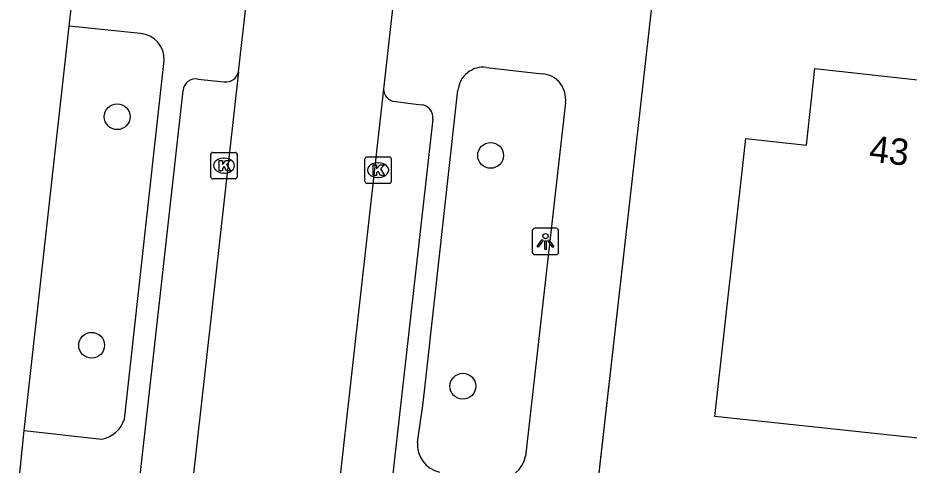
# Model space of a CAD drawing. Extents: x 162026 to 163499, y 387297 to 388169.
# Drawn here: x 162278.65 to 162312.4, y 387793.2 to 387810.16 of the extents above; entities that cross this region are included whole.
import ezdxf

# ---------------------------------------------------------------- set-up
doc = ezdxf.new("R2010")
doc.units = 0
for name, color, linetype in [('IMGEO_Boom', 7, 'Continuous'), ('IMGEO_Fietspad_gesloten', 7, 'Continuous'), ('IMGEO_Kolk', 7, 'Continuous'), ('IMGEO_Lichtpunt', 7, 'Continuous'), ('IMGEO_Muur', 7, 'Continuous'), ('IMGEO_Pand', 7, 'Continuous'), ('IMGEO_Pand_nummerreeks', 7, 'Continuous'), ('IMGEO_Rijbaan_lokaal_gesloten', 7, 'Continuous'), ('IMGEO_Voetpad_open', 7, 'Continuous')]:
    doc.layers.add(name, color=color, linetype=linetype)

msp = doc.modelspace()

# ---------------------------------------------------------------- linework, layer by layer
at = {"layer": 'IMGEO_Boom'}
for centre in [(162282.408, 387806.409), (162296.549, 387804.942), (162281.44, 387797.746), (162295.498, 387796.193)]:
    msp.add_circle(centre, 0.489, dxfattribs=at)
at = {"layer": 'IMGEO_Fietspad_gesloten'}
for points in [[(162280.59, 387809.842), (162281.546, 387818.246), (162282.058, 387818.211)], [(162278.879, 387794.52), (162280.59, 387809.842)], [(162278.652, 387792.276), (162278.879, 387794.52)]]:
    msp.add_lwpolyline(points, dxfattribs=at)
at = {"layer": 'IMGEO_Kolk'}
for p, q in [((162285.95, 387804.129), (162285.95, 387804.981)), ((162286.025, 387805.055), (162286.877, 387805.055)), ((162286.438, 387804.835), (162286.463, 387804.835)), ((162286.951, 387804.981), (162286.951, 387804.129)), ((162291.786, 387803.957), (162291.786, 387804.809)), ((162291.861, 387804.883), (162292.713, 387804.883)), ((162292.787, 387804.809), (162292.787, 387803.957)), ((162292.274, 387804.663), (162292.299, 387804.663)), ((162286.461, 387804.275), (162286.436, 387804.275)), ((162292.297, 387804.103), (162292.272, 387804.103)), ((162286.877, 387804.055), (162286.025, 387804.055)), ((162292.713, 387803.883), (162291.861, 387803.883))]:
    msp.add_line(p, q, dxfattribs=at)
for points in [[(162285.95, 387804.129), (162285.95, 387804.981)], [(162286.025, 387805.055), (162286.877, 387805.055)], [(162286.951, 387804.981), (162286.951, 387804.129)], [(162291.786, 387803.957), (162291.786, 387804.809)], [(162291.861, 387804.883), (162292.713, 387804.883)], [(162292.787, 387804.809), (162292.787, 387803.957)], [(162286.271, 387804.755), (162286.394, 387804.755), (162286.394, 387804.604), (162286.524, 387804.755), (162286.688, 387804.755), (162286.542, 387804.604), (162286.695, 387804.355), (162286.543, 387804.355), (162286.458, 387804.519), (162286.394, 387804.452), (162286.394, 387804.355), (162286.271, 387804.355), (162286.271, 387804.755)], [(162292.107, 387804.583), (162292.23, 387804.583), (162292.23, 387804.432), (162292.36, 387804.583), (162292.524, 387804.583), (162292.378, 387804.432), (162292.531, 387804.183), (162292.379, 387804.183), (162292.294, 387804.347), (162292.23, 387804.28), (162292.23, 387804.183), (162292.107, 387804.183), (162292.107, 387804.583)], [(162286.877, 387804.055), (162286.025, 387804.055)], [(162292.713, 387803.883), (162291.861, 387803.883)]]:
    msp.add_lwpolyline(points, dxfattribs=at)
for centre, start, end in [((162286.027, 387804.979), 91.552, 178.448), ((162286.027, 387804.979), 91.552, 178.448), ((162286.875, 387804.979), 1.552, 88.448), ((162286.875, 387804.979), 1.552, 88.448), ((162291.863, 387804.807), 91.552, 178.448), ((162291.863, 387804.807), 91.552, 178.448), ((162292.711, 387804.807), 1.552, 88.448), ((162292.711, 387804.807), 1.552, 88.448), ((162286.027, 387804.131), 181.552, 268.448), ((162286.027, 387804.131), 181.552, 268.448), ((162286.875, 387804.131), 271.552, 358.448), ((162286.875, 387804.131), 271.552, 358.448), ((162291.863, 387803.959), 181.552, 268.448), ((162291.863, 387803.959), 181.552, 268.448), ((162292.711, 387803.959), 271.552, 358.448), ((162292.711, 387803.959), 271.552, 358.448)]:
    msp.add_arc(centre, 0.0765, start, end, dxfattribs=at)
for centre, major_axis, ratio, start_param, end_param in [((162286.437, 387804.555), (-0.387, 0.002), 0.722429, 4.712389, 7.853982), ((162286.462, 387804.555), (-0.39, 0.002), 0.717154, 1.570796, 4.712389), ((162292.273, 387804.383), (-0.387, 0.002), 0.722429, 4.712389, 7.853982), ((162292.298, 387804.383), (-0.39, 0.002), 0.717154, 1.570796, 4.712389)]:
    msp.add_ellipse(centre, major_axis=major_axis, ratio=ratio, start_param=start_param, end_param=end_param, dxfattribs=at)
at = {"layer": 'IMGEO_Lichtpunt'}
for p, q in [((162298.128, 387802.085), (162298.128, 387801.278)), ((162298.128, 387802.085), (162298.128, 387801.278)), ((162299.03, 387802.18), (162298.222, 387802.18)), ((162299.03, 387802.18), (162298.222, 387802.18)), ((162299.124, 387801.278), (162299.124, 387802.085)), ((162299.124, 387801.278), (162299.124, 387802.085)), ((162298.222, 387801.184), (162299.03, 387801.184)), ((162298.222, 387801.184), (162299.03, 387801.184))]:
    msp.add_line(p, q, dxfattribs=at)
for points in [[(162298.502, 387801.749), (162298.541, 387801.721), (162298.353, 387801.459), (162298.315, 387801.486), (162298.502, 387801.749)], [(162298.714, 387801.721), (162298.752, 387801.748), (162298.939, 387801.486), (162298.9, 387801.458), (162298.714, 387801.721)], [(162298.604, 387801.701), (162298.651, 387801.701), (162298.651, 387801.379), (162298.604, 387801.379), (162298.604, 387801.701)]]:
    msp.add_lwpolyline(points, dxfattribs=at)
msp.add_circle((162298.627, 387801.883), 0.0994, dxfattribs=at)
for centre, start, end in [((162298.222, 387802.085), 90, 180), ((162298.222, 387802.085), 90, 180), ((162299.03, 387802.085), 0, 90), ((162299.03, 387802.085), 0, 90), ((162298.222, 387801.278), 180, 270), ((162298.222, 387801.278), 180, 270), ((162299.03, 387801.278), 270, 0), ((162299.03, 387801.278), 270, 360)]:
    msp.add_arc(centre, 0.0946, start, end, dxfattribs=at)
at = {"layer": 'IMGEO_Muur'}
msp.add_lwpolyline([(162300.27, 387789.459), (162302.135, 387805.96)], dxfattribs=at)
at = {"layer": 'IMGEO_Pand'}
msp.add_lwpolyline([(162314.61, 387799.534), (162314.475, 387798.313), (162314.036, 387794.079), (162305.036, 387795.05), (162306.214, 387805.585), (162308.506, 387805.337), (162308.825, 387808.234), (162315.35, 387807.516)], dxfattribs=at)
at = {"layer": 'IMGEO_Rijbaan_lokaal_gesloten'}
for points in [[(162287.006, 387808.114), (162287.762, 387814.78)], [(162292.904, 387811.196), (162292.493, 387807.458)], [(162287.006, 387808.114), (162280.695, 387751.699), (162277.051, 387719.431), (162275.389, 387704.712)], [(162292.493, 387807.458), (162285.406, 387744.3), (162281.03, 387705.382)]]:
    msp.add_lwpolyline(points, dxfattribs=at)
at = {"layer": 'IMGEO_Voetpad_open'}
for points in [[(162300.281, 387789.552), (162302.135, 387805.96), (162302.745, 387811.357)], [(162283.29, 387809.569), (162280.59, 387809.842)], [(162282.682, 387794.949), (162284.192, 387808.546)], [(162296.389, 387808.281), (162298.505, 387808.039)], [(162285.462, 387807.834), (162286.46, 387807.73)], [(162273.411, 387704.935), (162278.703, 387751.857), (162284.902, 387807.407)], [(162293.785, 387794.073), (162293.984, 387795.465), (162294.044, 387796.005), (162295.313, 387807.419)], [(162292.929, 387806.99), (162293.929, 387806.859)], [(162299.382, 387806.943), (162297.989, 387794.536), (162297.868, 387793.536)], [(162294.36, 387806.319), (162292.997, 387794.228), (162292.495, 387789.737), (162287.384, 387743.942), (162283.154, 387706.135)], [(162278.879, 387794.52), (162281.83, 387794.192)]]:
    msp.add_lwpolyline(points, dxfattribs=at)
for centre, radius, start, end in [((162283.197, 387808.578), 0.995, 358.159, 84.6476), ((162296.276, 387807.32), 0.968, 83.2855, 174.112), ((162285.374, 387807.369), 0.473, 79.2655, 175.3856), ((162286.517, 387808.229), 0.502, 263.4722, 346.765), ((162298.425, 387807.076), 0.966, 352.0641, 85.2682), ((162292.954, 387807.45), 0.461, 179.04, 266.9053), ((162293.896, 387806.391), 0.469, 351.1919, 85.9983), ((162281.627, 387795.278), 1.105, 280.573, 342.669), ((162294.853, 387793.976), 1.072, 174.8111, 257.0107), ((162296.843, 387793.727), 1.042, 267.4004, 349.4221)]:
    msp.add_arc(centre, radius, start, end, dxfattribs=at)

# ---------------------------------------------------------------- texts
at = {"layer": 'IMGEO_Pand_nummerreeks'}
msp.add_text('43', height=1, rotation=353.7219, dxfattribs=at).set_placement((162310.852, 387804.711))

doc.saveas('drawing.dxf')
